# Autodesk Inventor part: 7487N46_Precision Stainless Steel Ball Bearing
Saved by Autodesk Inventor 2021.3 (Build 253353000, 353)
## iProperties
Created: 2022-05
Part Number: 7487N46_Precision Stainless Steel Ball Bearing
Material: Generic
Document SubType Name: Modeling
Designer: Administrator
Density: 1 g/cm^3
Appearance: Default
Title: 7487N46_Precision Stainless Steel Ball Bearing
Author: Administrator
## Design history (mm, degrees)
feature "Body1"
feature "Body2"
feature "Body3"
feature "Body4"
feature "Body5"
feature "Body6"
feature "Body7"
feature "Body8"
feature "Body9"
feature "Body10"
feature "Body11"
feature "Body12"
feature "Body13"
body "Solid1"
body "Solid2"
body "Solid3"
body "Solid4"
body "Solid5"
body "Solid6"
body "Solid7"
body "Solid8"
body "Solid9"
body "Solid10"
body "Solid11"
body "Solid12"
body "Solid13"
